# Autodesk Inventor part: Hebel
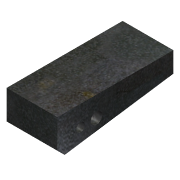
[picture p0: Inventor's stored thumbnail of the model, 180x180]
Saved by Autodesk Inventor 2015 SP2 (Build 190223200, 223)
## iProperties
Created: 2017-07
Part Number: Hebel
Material: St
Document SubType Name: Modeling
Designer: UR
Density: 7.85 g/cm^3
Appearance: Platte
Mass: 443.221 g
Surface Area: 118.227 cm^2
Volume: 56.4613 cm^3
Author: UR
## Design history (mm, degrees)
sketch "Skizze1"
  geometry: L1 (0, 0)-(0, -20); L2 (0, -20)-(5, -25); L3 (5, -25)-(80, -14); L4 (80, -14)-(80, 0); L5 (80, 0)-(0, 0)
  constraints: 10 end point, 1 parallel, 1 perpendicular, 1 vertical
  dimensions: "d0" = 80 distance of L4.end L1.start; "d1" = 14 distance of L3.end L4.end; "d2" = 25 distance from line of L5 L2.end; "d3" = 5 horizontal distance of L2.end L1.end; "d4" = 45 deg angle of L1 L2
extrude "Grundkörper" new body sketch "Skizze1" stored distance "d5" = 35; taper "d6" = 0 deg
sketch "Skizze für Querbohrungen"
  geometry: L1 (0, 0)-(20, 0) reference; L2 (0, 80)-(0, 0) reference; 2 further points
  dimensions: "d7" = 16 distance from line of L1 point (14, 16); "d8" = 27 distance from line of L1 point (14, 27); "d9" = 14 distance from line of point (14, 16) L2; "d10" = 14 distance from line of point (14, 27) L2
hole "Bohrung für Hebelachse" sketch "Skizze für Querbohrungen" diameter "d11" = 6; stored, may be unused: countersink angle "d15" = 90 deg, drill point angle "d17" = 118 deg; dims "d12" = 6, "d13" = 4, "d14" = 2, "d16" = 8
hole "Bohrung für Druckstift" sketch "Skizze für Querbohrungen" diameter "d18" = 8; stored, may be unused: countersink angle "d22" = 90 deg, drill point angle "d24" = 118 deg; dims "d19" = 6, "d20" = 4, "d21" = 2, "d23" = 8
sketch "Skizze3"
  geometry: L1 (35, -48.439)-(0, -48.439) reference; L2 (35, -56.439)-(0, -56.439) reference; L3 (0, -56.439)-(35, -48.439); 2 further points
  constraints: 2 end point, 1 midpoint
hole "M4 für Gewindestift" sketch "Skizze3" at (17.5, -52.439) diameter "d25" = 3.242; stored, may be unused: countersink angle "d29" = 82 deg, drill point angle "d31" = 118 deg; dims "d26" = 8, "d27" = 3.023, "d28" = 2, "d30" = 11.8
node "Mittelebene yz"
node "Volumenkörper1"
